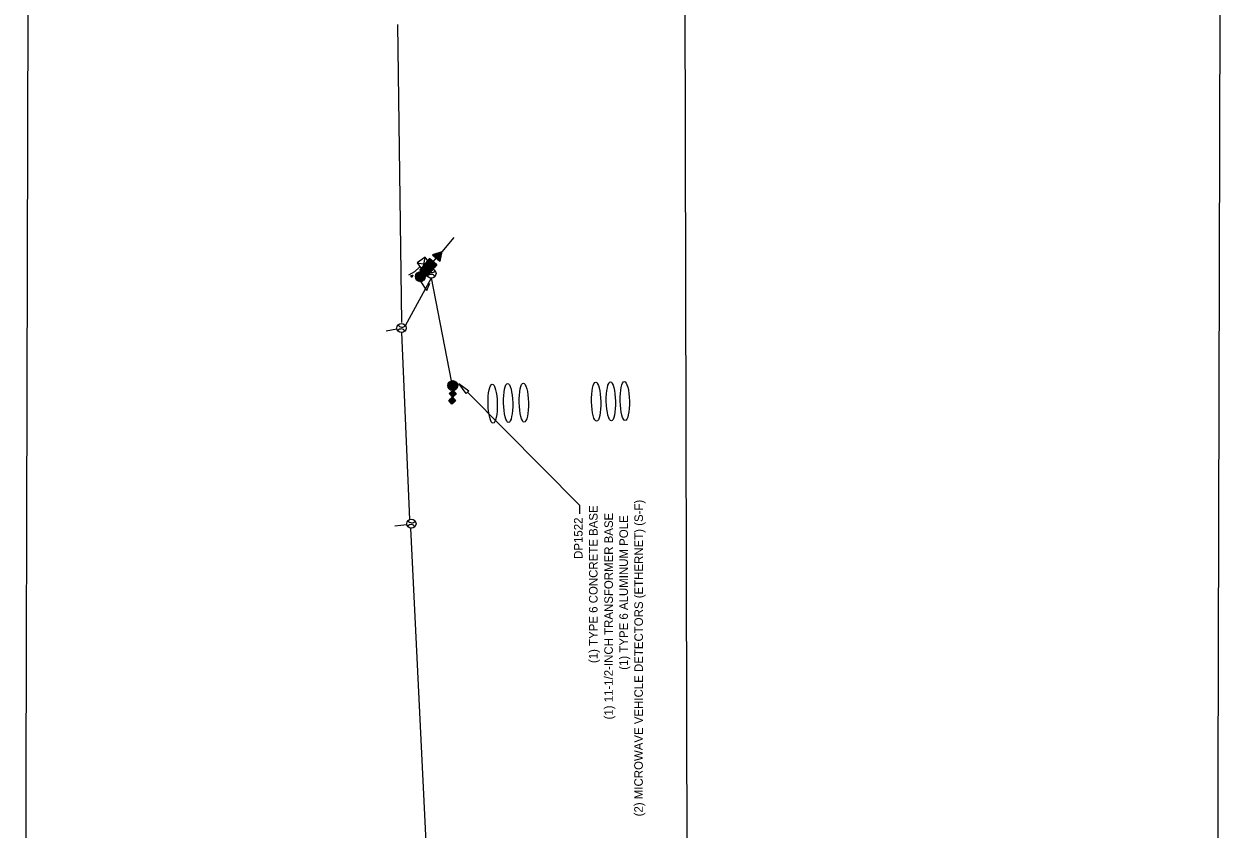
# Model space of a CAD drawing. Extents: x 601462 to 605493, y 331960 to 402715.
# Drawn here: x 602790 to 603769, y 376234 to 376893 of the extents above; entities that cross this region are included whole.
import ezdxf

# ---------------------------------------------------------------- set-up
doc = ezdxf.new("R2010")
doc.units = 0
for name, color, linetype in [('Default', 7, 'Continuous'), ('P_FTMS', 7, 'Continuous'), ('P_FTMSConduit', 7, 'Continuous'), ('P_MISC_TXT_1A (Construction)', 7, 'Continuous')]:
    doc.layers.add(name, color=color, linetype=linetype)

# ---------------------------------------------------------------- blocks, each defined once
blk = doc.blocks.new('FMB')
at = {"layer": 'P_FTMS'}
for p, q in [((24.4, -24.4), (-24.4, 24.4)), ((-24.4, -24.4), (24.4, 24.4))]:
    blk.add_line(p, q, dxfattribs=at)
blk.add_lwpolyline([(24.4, -24.4), (24.4, 24.4), (-24.4, 24.4), (-24.4, -24.4)], close=True, dxfattribs=at)
blk = doc.blocks.new('POINT_DISPLAY')
at = {"layer": 'Default'}
blk.add_line((0, 0), (0, 0), dxfattribs=at)
blk = doc.blocks.new('_U229')
at = {"layer": 'P_FTMS'}
for p, q in [((-4.5, 3.2), (1.5, -0.2)), ((-4.4, 2.8), (1.3, -0.4)), ((-4.3, 3.5), (1.8, 0)), ((-3.9, 3.4), (-4.3, 2.6)), ((-4.3, 2.4), (1, -0.6)), ((-3.5, 3.4), (-4.2, 2.2)), ((-4.2, 2), (0.7, -0.8)), ((-3.2, 3.3), (-4.1, 1.7)), ((-4.1, 1.6), (0.5, -1)), ((-2.9, 3.3), (-4, 1.3)), ((-4, 1.2), (0.2, -1.2)), ((-2.6, 3.2), (-3.9, 0.9)), ((-2.2, 3.2), (-3.8, 0.5)), ((-3.8, 0.7), (0, -1.4)), ((-1.9, 3.2), (-3.7, 0.1)), ((-3.7, 0.3), (-0.3, -1.6)), ((-3.5, 3.4), (2, 0.2)), ((-1.6, 3.1), (-3.5, -0.3)), ((-1.3, 3.1), (-3.4, -0.7)), ((-0.9, 3), (-3.3, -1.2)), ((-0.6, 3), (-3.2, -1.6)), ((-0.3, 2.9), (-3.1, -2)), ((0, 2.9), (-3, -2.4)), ((0.4, 2.8), (-2.9, -2.8)), ((-2.7, 3.3), (2.3, 0.4)), ((0.7, 2.8), (-2.7, -3.2)), ((1, 2.8), (-2.5, -3.4)), ((-1.9, 3.2), (2.5, 0.6)), ((1.3, 2.7), (-1.8, -2.9)), ((1.7, 2.7), (-1.2, -2.3)), ((-1.1, 3), (2.8, 0.8)), ((2, 2.6), (-0.5, -1.8)), ((-0.3, 2.9), (3.1, 1)), ((2.3, 2.6), (0.1, -1.3)), ((0.5, 2.8), (3.3, 1.2)), ((2.6, 2.5), (0.7, -0.8)), ((1.3, 2.7), (3.6, 1.4)), ((3, 2.5), (1.4, -0.3)), ((3.3, 2.4), (2, 0.2)), ((2.2, 2.6), (3.8, 1.6)), ((3.6, 2.4), (2.7, 0.7)), ((3, 2.5), (4.1, 1.8)), ((3.9, 2.3), (3.3, 1.2)), ((3.8, 2.4), (4.3, 2.1)), ((4.3, 2.3), (4, 1.7)), ((-3.6, -0.1), (-0.5, -1.8)), ((-3.5, -0.5), (-0.8, -2)), ((-3.4, -0.9), (-1.1, -2.2)), ((-3.3, -1.3), (-1.3, -2.4)), ((-3.2, -1.7), (-1.6, -2.7)), ((-3, -2.2), (-1.8, -2.9)), ((-2.9, -2.6), (-2.1, -3.1)), ((-2.8, -3), (-2.3, -3.3)), ((-2.7, -3.4), (-2.6, -3.5))]:
    blk.add_line(p, q, dxfattribs=at)
blk.add_lwpolyline([(-4.6, 3.5), (4.6, 2.3), (-2.7, -3.5)], close=True, dxfattribs=at)
blk.add_blockref('POINT_DISPLAY', (4.6, 2.3), dxfattribs=at)
blk = doc.blocks.new('_U231')
at = {"layer": 'P_FTMS'}
for p, q in [((12.1, 1.6), (-12.2, -0.1)), ((11.8, 3), (-12.1, 1.4)), ((11.9, 2.3), (-12.1, 0.6)), ((12.1, 0.8), (-12.1, -0.8)), ((12.1, 0.1), (-12.1, -1.6)), ((11.6, 3.7), (-12, 2.1)), ((-11.9, 2.5), (-11.4, -4.2)), ((11.3, 4.4), (-11.8, 2.9)), ((11, 5.2), (-11.6, 3.6)), ((10.6, 5.9), (-11.4, 4.4)), ((-11.3, 4.5), (-10.6, -6)), ((10.2, 6.6), (-11, 5.1)), ((9.8, 7.3), (-10.7, 5.9)), ((-10.7, 5.9), (-9.8, -7.2)), ((9.2, 8), (-10.2, 6.6)), ((-10, 6.9), (-9, -8.2)), ((8.6, 8.6), (-9.7, 7.4)), ((-9.3, 7.8), (-8.2, -9)), ((7.8, 9.3), (-9, 8.2)), ((-8.6, 8.5), (-7.4, -9.6)), ((6.9, 10), (-8.2, 9)), ((-8, 9.2), (-6.6, -10.2)), ((-7.3, 9.7), (-5.9, -10.6)), ((5.8, 10.7), (-7.2, 9.8)), ((-6.6, 10.3), (-5.1, -11)), ((4.5, 11.3), (-6, 10.6)), ((-5.9, 10.7), (-4.4, -11.4)), ((-5.1, 11), (-3.6, -11.6)), ((-4.4, 11.3), (-2.9, -11.8)), ((2.5, 11.9), (-4.1, 11.5)), ((-3.7, 11.6), (-2.1, -12)), ((-3, 11.8), (-1.4, -12.1)), ((-2.3, 12), (-0.6, -12.2)), ((-1.6, 12.1), (0.1, -12.2)), ((-0.8, 12.1), (0.8, -12.1)), ((-0.1, 12.2), (1.6, -12.1)), ((0.6, 12.1), (2.3, -11.9)), ((1.4, 12.1), (3, -11.8)), ((2.1, 12), (3.7, -11.6)), ((2.9, 11.8), (4.4, -11.3)), ((3.6, 11.6), (5.1, -11)), ((4.4, 11.3), (5.9, -10.7)), ((5.1, 11), (6.6, -10.2)), ((5.9, 10.6), (7.3, -9.8)), ((6.6, 10.2), (8, -9.2)), ((7.4, 9.7), (8.6, -8.6)), ((8.2, 9), (9.3, -7.8)), ((9, 8.2), (10, -6.9)), ((9.8, 7.2), (10.7, -5.8)), ((10.6, 5.9), (11.3, -4.5)), ((11.5, 4), (11.9, -2.5)), ((12.1, -0.6), (-12, -2.3)), ((12.1, -1.4), (-11.8, -3)), ((12, -2.1), (-11.6, -3.7)), ((11.8, -2.9), (-11.3, -4.4)), ((11.6, -3.6), (-11, -5.1)), ((11.3, -4.4), (-10.7, -5.9)), ((11.1, -5.1), (-10.2, -6.6)), ((10.6, -5.9), (-9.8, -7.3)), ((10.2, -6.6), (-9.2, -8)), ((9.6, -7.4), (-8.5, -8.6)), ((9, -8.2), (-7.8, -9.3)), ((8.2, -9), (-6.9, -10)), ((7.3, -9.8), (-5.8, -10.7)), ((6, -10.6), (-4.5, -11.3)), ((4.1, -11.5), (-2.6, -11.9))]:
    blk.add_line(p, q, dxfattribs=at)
blk.add_circle((0, 0), 12.2, dxfattribs=at)
blk = doc.blocks.new('FMD')
at = {"layer": 'P_FTMS'}
for p, q in [((16.9, 17.6), (-16.9, 17.6)), ((-16.1, 16.1), (-16.1, 18.4)), ((16.1, 16.1), (-16.1, 16.1)), ((15.5, 19), (-15.5, 19)), ((-14.6, 14.6), (-14.6, 19.9)), ((14.6, 14.6), (-14.6, 14.6)), ((14, 20.5), (-14, 20.5)), ((-13.2, 13.2), (-13.2, 21.3)), ((13.2, 13.2), (-13.2, 13.2)), ((12.5, 21.9), (-12.5, 21.9)), ((-11.7, 11.7), (-11.7, 22.8)), ((11.7, 11.7), (-11.7, 11.7)), ((11.1, 23.4), (-11.1, 23.4)), ((-10.2, 10.2), (-10.2, 24.2)), ((10.2, 10.2), (-10.2, 10.2)), ((9.6, 24.9), (-9.6, 24.9)), ((-8.8, 8.8), (-8.8, 25.7)), ((8.8, 8.8), (-8.8, 8.8)), ((8.2, 26.3), (-8.2, 26.3)), ((-7.3, 7.3), (-7.3, 27.2)), ((7.3, 7.3), (-7.3, 7.3)), ((6.7, 27.8), (-6.7, 27.8)), ((-5.9, 5.9), (-5.9, 28.6)), ((5.9, 5.9), (-5.9, 5.9)), ((5.2, 29.3), (-5.2, 29.3)), ((-4.4, 4.4), (-4.4, 30.1)), ((4.4, 4.4), (-4.4, 4.4)), ((3.8, 30.7), (-3.8, 30.7)), ((-2.9, 2.9), (-2.9, 31.6)), ((2.9, 2.9), (-2.9, 2.9)), ((2.3, 32.2), (-2.3, 32.2)), ((-1.5, 1.5), (-1.5, 33)), ((1.5, 1.5), (-1.5, 1.5)), ((0.8, 33.6), (-0.8, 33.6)), ((0, 0), (0, 34.5)), ((1.5, 1.5), (1.5, 33)), ((2.9, 2.9), (2.9, 31.6)), ((4.4, 4.4), (4.4, 30.1)), ((5.9, 5.9), (5.9, 28.6)), ((7.3, 7.3), (7.3, 27.2)), ((8.8, 8.8), (8.8, 25.7)), ((10.2, 10.2), (10.2, 24.2)), ((11.7, 11.7), (11.7, 22.8)), ((13.2, 13.2), (13.2, 21.3)), ((14.6, 14.6), (14.6, 19.9)), ((16.1, 16.1), (16.1, 18.4))]:
    blk.add_line(p, q, dxfattribs=at)
blk.add_lwpolyline([(-17.2, 17.2), (0, 34.5), (17.2, 17.2), (0, 0)], close=True, dxfattribs=at)

msp = doc.modelspace()

# ---------------------------------------------------------------- linework, layer by layer
at = {"layer": 'P_FTMS'}
for p, q in [((603141.66, 376718.23), (603131.72, 376706.73)), ((603119.37, 376698.52), (603124.15, 376698.87)), ((603119.59, 376698.78), (603123.9, 376699.09)), ((603119.59, 376698.78), (603120.41, 376687.5)), ((603119.81, 376699.04), (603123.64, 376699.32)), ((603119.81, 376699.04), (603120.63, 376687.75)), ((603120.03, 376699.29), (603123.38, 376699.54)), ((603120.03, 376699.29), (603120.85, 376688.01)), ((603120.25, 376699.55), (603123.13, 376699.76)), ((603120.25, 376699.55), (603121.08, 376688.27)), ((603120.48, 376699.81), (603122.87, 376699.98)), ((603120.48, 376699.81), (603121.3, 376688.52)), ((603120.7, 376700.06), (603122.61, 376700.2)), ((603120.7, 376700.06), (603121.52, 376688.78)), ((603120.92, 376700.32), (603122.36, 376700.43)), ((603120.92, 376700.32), (603121.74, 376689.04)), ((603121.14, 376700.58), (603122.1, 376700.65)), ((603121.14, 376700.58), (603121.96, 376689.29)), ((603121.36, 376700.83), (603121.84, 376700.87)), ((603121.36, 376700.83), (603122.19, 376689.55)), ((603121.58, 376701.09), (603122.41, 376689.81)), ((603121.84, 376700.87), (603122.63, 376690.06)), ((603122.1, 376700.65), (603122.85, 376690.32)), ((603122.36, 376700.43), (603123.07, 376690.58)), ((603122.61, 376700.2), (603123.3, 376690.83)), ((603122.87, 376699.98), (603123.52, 376691.09)), ((603123.13, 376699.76), (603123.74, 376691.35)), ((603123.38, 376699.54), (603123.96, 376691.6)), ((603123.64, 376699.32), (603124.18, 376691.86)), ((603123.9, 376699.09), (603124.41, 376692.12)), ((603124.15, 376698.87), (603124.63, 376692.38)), ((603124.21, 376704.12), (603124.21, 376704.11)), ((603124.31, 376704.02), (603131.3, 376704.53)), ((603124.44, 376704.2), (603124.47, 376703.89)), ((603124.57, 376703.8), (603131.25, 376704.29)), ((603124.61, 376698.48), (603127.23, 376701.5)), ((603124.68, 376704.28), (603124.72, 376703.66)), ((603124.7, 376704.29), (603131.35, 376704.78)), ((603124.82, 376703.58), (603131.21, 376704.05)), ((603124.91, 376704.36), (603124.98, 376703.44)), ((603125.08, 376703.36), (603131.16, 376703.8)), ((603125.15, 376704.45), (603125.24, 376703.22)), ((603125.34, 376703.14), (603131.11, 376703.56)), ((603125.38, 376704.53), (603125.49, 376703)), ((603125.58, 376704.6), (603131.39, 376705.02)), ((603125.59, 376702.91), (603131.07, 376703.31)), ((603125.62, 376704.61), (603125.75, 376702.78)), ((603125.85, 376704.69), (603126.01, 376702.55)), ((603125.85, 376702.69), (603131.02, 376703.07)), ((603126.09, 376704.77), (603126.26, 376702.33)), ((603126.11, 376702.47), (603130.97, 376702.82)), ((603126.32, 376704.85), (603126.52, 376702.11)), ((603126.36, 376702.25), (603130.93, 376702.58)), ((603126.46, 376704.9), (603131.44, 376705.27)), ((603126.56, 376704.94), (603126.78, 376701.89)), ((603126.62, 376702.03), (603130.88, 376702.34)), ((603126.79, 376705.02), (603127.04, 376701.67)), ((603126.88, 376701.8), (603130.83, 376702.09)), ((603127.03, 376705.1), (603127.29, 376701.45)), ((603127.13, 376701.58), (603130.79, 376701.85)), ((603127.26, 376705.18), (603127.55, 376701.22)), ((603127.34, 376705.21), (603131.49, 376705.51)), ((603127.39, 376701.36), (603130.74, 376701.6)), ((603127.49, 376705.26), (603127.81, 376701)), ((603127.65, 376701.14), (603130.69, 376701.36)), ((603127.73, 376705.34), (603128.06, 376700.78)), ((603127.9, 376700.92), (603130.65, 376701.12)), ((603127.96, 376705.43), (603128.32, 376700.56)), ((603128.16, 376700.69), (603130.6, 376700.87)), ((603128.2, 376705.51), (603128.58, 376700.34)), ((603128.21, 376705.51), (603131.53, 376705.75)), ((603128.42, 376700.47), (603130.55, 376700.63)), ((603128.43, 376705.59), (603128.83, 376700.11)), ((603128.67, 376705.67), (603129.09, 376699.89)), ((603128.67, 376700.25), (603130.51, 376700.38)), ((603128.9, 376705.75), (603129.35, 376699.67)), ((603128.93, 376700.03), (603130.46, 376700.14)), ((603129.09, 376705.82), (603131.58, 376706)), ((603129.14, 376705.83), (603129.6, 376699.45)), ((603129.19, 376699.81), (603130.41, 376699.9)), ((603129.37, 376705.91), (603129.86, 376699.23)), ((603129.44, 376699.59), (603130.37, 376699.65)), ((603129.61, 376706), (603130.12, 376699)), ((603129.7, 376699.36), (603130.32, 376699.41)), ((603129.84, 376706.08), (603130.33, 376699.44)), ((603129.96, 376699.14), (603130.27, 376699.16)), ((603129.97, 376706.12), (603131.63, 376706.24)), ((603130.08, 376706.16), (603130.5, 376700.35)), ((603130.22, 376698.92), (603130.23, 376698.92)), ((603130.31, 376706.24), (603130.67, 376701.26)), ((603130.55, 376706.32), (603130.85, 376702.17)), ((603130.78, 376706.4), (603131.02, 376703.09)), ((603130.84, 376706.43), (603131.67, 376706.49)), ((603131.01, 376706.48), (603131.2, 376704)), ((603131.25, 376706.57), (603131.37, 376704.91)), ((603131.48, 376706.65), (603131.54, 376705.82)), ((603131.72, 376706.73), (603131.72, 376706.73)), ((603110.8, 376688.53), (603117.15, 376688.99)), ((603110.97, 376688.78), (603116.95, 376689.22)), ((603111.08, 376688.91), (603111.48, 376683.41)), ((603111.19, 376689.04), (603116.69, 376689.44)), ((603111.3, 376689.16), (603111.74, 376683.19)), ((603111.44, 376689.3), (603116.41, 376689.66)), ((603111.52, 376689.37), (603111.99, 376683.02)), ((603111.75, 376689.56), (603112.24, 376682.85)), ((603111.76, 376689.56), (603116.04, 376689.88)), ((603111.98, 376689.72), (603112.49, 376682.74)), ((603112.18, 376689.83), (603115.6, 376690.08)), ((603112.21, 376689.85), (603112.74, 376682.63)), ((603112.44, 376689.98), (603112.99, 376682.55)), ((603112.68, 376690.07), (603113.23, 376682.49)), ((603112.81, 376690.12), (603114.95, 376690.28)), ((603112.91, 376690.16), (603113.48, 376682.43)), ((603113.15, 376690.24), (603113.72, 376682.4)), ((603113.38, 376690.28), (603113.96, 376682.39)), ((603113.62, 376690.32), (603114.2, 376682.37)), ((603113.82, 376692.1), (603125.1, 376692.92)), ((603113.82, 376692.1), (603113.83, 376691.93)), ((603113.86, 376690.35), (603114.44, 376682.39)), ((603113.9, 376691.87), (603124.88, 376692.67)), ((603114.04, 376692.36), (603125.32, 376693.18)), ((603114.04, 376692.36), (603114.09, 376691.71)), ((603114.1, 376690.35), (603114.68, 376682.41)), ((603114.16, 376691.65), (603124.66, 376692.41)), ((603114.26, 376692.62), (603125.55, 376693.44)), ((603114.26, 376692.62), (603114.34, 376691.49)), ((603114.34, 376690.36), (603114.92, 376682.45)), ((603114.42, 376691.42), (603124.44, 376692.15)), ((603114.48, 376692.87), (603125.77, 376693.7)), ((603114.48, 376692.87), (603114.6, 376691.26)), ((603114.58, 376690.34), (603115.15, 376682.51)), ((603114.67, 376691.2), (603124.21, 376691.9)), ((603114.71, 376693.13), (603125.99, 376693.95)), ((603114.71, 376693.13), (603114.86, 376691.04)), ((603114.83, 376690.3), (603115.39, 376682.57)), ((603114.93, 376693.39), (603126.21, 376694.21)), ((603114.93, 376693.39), (603115.12, 376690.82)), ((603114.93, 376690.98), (603123.99, 376691.64)), ((603115.07, 376690.26), (603115.62, 376682.66)), ((603115.15, 376693.64), (603126.43, 376694.47)), ((603115.15, 376693.64), (603115.37, 376690.6)), ((603115.19, 376690.76), (603123.77, 376691.38)), ((603115.32, 376690.18), (603115.86, 376682.77)), ((603115.37, 376693.9), (603126.66, 376694.72)), ((603115.37, 376693.9), (603115.63, 376690.38)), ((603115.45, 376690.54), (603123.55, 376691.13)), ((603115.56, 376690.1), (603116.09, 376682.87)), ((603115.59, 376694.16), (603126.88, 376694.98)), ((603115.59, 376694.16), (603115.89, 376690.16)), ((603115.7, 376690.31), (603123.33, 376690.87)), ((603115.81, 376690), (603116.32, 376683.02)), ((603115.82, 376694.41), (603127.1, 376695.24)), ((603115.82, 376694.41), (603116.14, 376689.93)), ((603115.96, 376690.09), (603123.11, 376690.61)), ((603116.04, 376694.67), (603127.32, 376695.49)), ((603116.04, 376694.67), (603116.4, 376689.71)), ((603116.06, 376689.87), (603116.55, 376683.18)), ((603116.22, 376689.87), (603122.88, 376690.36)), ((603116.26, 376694.93), (603127.54, 376695.75)), ((603116.26, 376694.93), (603116.66, 376689.49)), ((603116.31, 376689.73), (603116.78, 376683.36)), ((603116.47, 376689.65), (603122.66, 376690.1)), ((603116.48, 376695.18), (603127.49, 376695.99)), ((603116.48, 376695.18), (603116.91, 376689.27)), ((603116.57, 376689.54), (603117, 376683.58)), ((603116.7, 376695.44), (603127.24, 376696.21)), ((603116.7, 376695.44), (603117.17, 376689.05)), ((603116.73, 376689.43), (603122.44, 376689.84)), ((603116.82, 376689.34), (603117.22, 376683.82)), ((603116.93, 376695.7), (603126.98, 376696.43)), ((603116.93, 376695.7), (603117.43, 376688.82)), ((603116.99, 376689.2), (603122.22, 376689.59)), ((603117.08, 376689.07), (603117.44, 376684.12)), ((603117.15, 376695.95), (603126.72, 376696.65)), ((603117.15, 376695.95), (603117.68, 376688.6)), ((603117.24, 376688.98), (603122, 376689.33)), ((603117.37, 376696.21), (603126.46, 376696.87)), ((603117.37, 376696.21), (603117.94, 376688.38)), ((603117.5, 376688.76), (603121.77, 376689.07)), ((603117.59, 376696.47), (603126.21, 376697.1)), ((603117.59, 376696.47), (603118.2, 376688.16)), ((603117.81, 376696.72), (603125.95, 376697.32)), ((603117.81, 376696.72), (603118.45, 376687.94)), ((603118.03, 376696.98), (603125.69, 376697.54)), ((603118.03, 376696.98), (603118.71, 376687.71)), ((603118.26, 376697.24), (603125.44, 376697.76)), ((603118.26, 376697.24), (603118.97, 376687.49)), ((603118.48, 376697.49), (603125.18, 376697.98)), ((603118.48, 376697.49), (603119.22, 376687.27)), ((603118.7, 376697.75), (603124.92, 376698.21)), ((603118.7, 376697.75), (603119.48, 376687.05)), ((603118.92, 376698.01), (603124.67, 376698.43)), ((603118.92, 376698.01), (603119.74, 376686.83)), ((603119.14, 376698.27), (603124.41, 376698.65)), ((603119.14, 376698.27), (603119.97, 376686.98)), ((603119.37, 376698.52), (603120.19, 376687.24)), ((603119.89, 376693.01), (603119.72, 376692.81)), ((603119.89, 376693.01), (603119.89, 376693.01)), ((603124.41, 376698.65), (603124.85, 376692.63)), ((603124.67, 376698.43), (603125.07, 376692.89)), ((603124.92, 376698.21), (603125.29, 376693.15)), ((603125.18, 376697.98), (603125.51, 376693.4)), ((603125.44, 376697.76), (603125.74, 376693.66)), ((603125.69, 376697.54), (603125.96, 376693.92)), ((603125.95, 376697.32), (603126.18, 376694.17)), ((603126.21, 376697.1), (603126.4, 376694.43)), ((603126.46, 376696.87), (603126.62, 376694.69)), ((603126.72, 376696.65), (603126.85, 376694.94)), ((603126.98, 376696.43), (603127.07, 376695.2)), ((603127.24, 376696.21), (603127.29, 376695.46)), ((603127.49, 376695.99), (603127.51, 376695.71)), ((603110.16, 376686.32), (603118.11, 376686.9)), ((603110.17, 376686.56), (603118.06, 376687.13)), ((603110.17, 376686.08), (603118.13, 376686.66)), ((603110.18, 376686.8), (603118.01, 376687.37)), ((603110.2, 376685.84), (603118.14, 376686.42)), ((603110.22, 376687.04), (603117.95, 376687.61)), ((603110.23, 376685.6), (603118.14, 376686.18)), ((603110.24, 376687.15), (603110.4, 376685.01)), ((603110.27, 376687.29), (603117.85, 376687.84)), ((603110.29, 376685.36), (603118.11, 376685.94)), ((603110.33, 376687.53), (603117.76, 376688.07)), ((603110.36, 376685.13), (603118.08, 376685.69)), ((603110.42, 376687.78), (603117.64, 376688.31)), ((603110.44, 376687.81), (603110.69, 376684.39)), ((603110.44, 376684.89), (603118.03, 376685.45)), ((603110.52, 376688.03), (603117.49, 376688.54)), ((603110.55, 376684.66), (603117.96, 376685.2)), ((603110.64, 376688.27), (603110.96, 376683.99)), ((603110.65, 376688.28), (603117.35, 376688.77)), ((603110.67, 376684.43), (603117.89, 376684.96)), ((603110.8, 376684.2), (603117.78, 376684.71)), ((603110.86, 376688.62), (603111.22, 376683.65)), ((603110.97, 376683.97), (603117.65, 376684.46)), ((603111.14, 376683.74), (603117.51, 376684.21)), ((603111.36, 376683.52), (603117.32, 376683.95)), ((603111.6, 376683.29), (603117.12, 376683.7)), ((603111.9, 376683.08), (603116.85, 376683.44)), ((603112.23, 376682.86), (603116.54, 376683.17)), ((603112.7, 376682.65), (603116.15, 376682.9)), ((603113.35, 376682.46), (603115.54, 376682.62)), ((603117.34, 376688.78), (603117.66, 376684.47)), ((603117.62, 376688.34), (603117.87, 376684.89)), ((603117.76, 376688.54), (603121.55, 376688.82)), ((603117.9, 376687.73), (603118.06, 376685.54)), ((603118.01, 376688.32), (603121.33, 376688.56)), ((603118.27, 376688.09), (603121.11, 376688.3)), ((603118.53, 376687.87), (603120.89, 376688.05)), ((603118.78, 376687.65), (603120.66, 376687.79)), ((603119.04, 376687.43), (603120.44, 376687.53)), ((603119.3, 376687.21), (603120.22, 376687.27)), ((603119.55, 376686.99), (603120, 376687.02))]:
    msp.add_line(p, q, dxfattribs=at)
for points in [[(603119.79, 376686.78), (603127.64, 376695.86), (603121.58, 376701.09), (603113.74, 376692.01)], [(603124.2, 376704.12), (603130.22, 376698.91), (603131.72, 376706.73)]]:
    msp.add_lwpolyline(points, close=True, dxfattribs=at)
for centre, radius in [((603114.15, 376686.37), 4), ((603123.25, 376688.92), 3.75), ((603098.8, 376644.25), 3.75), ((603106.89, 376484.2), 3.75)]:
    msp.add_circle(centre, radius, dxfattribs=at)
for centre, start, end in [((603123.58, 376693.41), 212.62987, 318.88552), ((603122.92, 376684.44), 32.62987, 138.88552), ((603098.46, 376639.76), 32.62987, 138.88552), ((603099.13, 376648.74), 212.62987, 318.88552), ((603106.55, 376479.71), 32.62987, 138.88552), ((603107.22, 376488.69), 212.62987, 318.88552)]:
    msp.add_arc(centre, 3.75, start, end, dxfattribs=at)
for centre in [(603173.35, 376582.43), (603185.95, 376583.02), (603198.78, 376583.31), (603257.98, 376583.97), (603270.02, 376584.24), (603281.37, 376584.49)]:
    msp.add_ellipse(centre, major_axis=(-0.36, 15.98), ratio=0.23471, dxfattribs=at)
at = {"layer": 'P_FTMSConduit'}
for p, q in [((603329.33, 377421.42), (603332.94, 375897.8)), ((603099.13, 376648.74), (603095.84, 376892.65)), ((603109.34, 376690.35), (603104.4, 376687.41)), ((603113.79, 376694.41), (603109.34, 376690.35)), ((603101.95, 376646.28), (603123.35, 376685.44)), ((603119.61, 376674.85), (603114.98, 376682.12)), ((603119.32, 376688.67), (603117.64, 376688.1)), ((603119.61, 376674.85), (603121.81, 376680.93)), ((603139.55, 376601.08), (603123.35, 376685.44)), ((603086.13, 376641.94), (603095.08, 376643.73)), ((603105.53, 376487.7), (603099, 376640.5)), ((603093.24, 376482.52), (603103.17, 376483.68)), ((603120.69, 376189.1), (603106.3, 376480.49))]:
    msp.add_line(p, q, dxfattribs=at)
msp.add_lwpolyline([(603151.55, 376590.62), (603145.71, 376598.9), (603153.92, 376592.97)], close=True, dxfattribs=at)
for points in [[(603152.74, 376591.8), (603244.22, 376499.35)], [(603244.22, 376499.35), (603244.21, 376492.35)]]:
    msp.add_lwpolyline(points, dxfattribs=at)
at = {"layer": 'P_MISC_TXT_1A (Construction)'}
msp.add_lwpolyline([(603764.98, 375644.6), (603769.03, 377219.59), (602794.03, 377222.1), (602789.98, 375647.11)], close=True, dxfattribs=at)
msp.add_lwpolyline([(603764.98, 375644.6), (603769.03, 377219.59), (602794.03, 377222.1), (602789.98, 375647.11)], close=True, dxfattribs=at)

# ---------------------------------------------------------------- block references
at = {"layer": 'P_FTMS'}
for name, p, xscale, yscale, rotation in [('FMB', (603117.06, 376696.72), 0.1640416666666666, 0.1640416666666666, -54.79289734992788), ('_U229', (603107.43, 376686.75), 0.19684999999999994, 0.19684999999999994, 20.861391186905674), ('_U231', (603140.7, 376597.25), 0.3280833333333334, 0.32808333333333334, 179.05577776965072), ('FMD', (603143.48, 376590.19), 0.16404166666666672, 0.16404166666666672, 84.94864200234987), ('FMD', (603143, 376584.59), 0.16404166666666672, 0.16404166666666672, 84.94864200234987)]:
    msp.add_blockref(name, p, dxfattribs=dict(at, xscale=xscale, yscale=yscale, rotation=rotation))

# ---------------------------------------------------------------- texts
at = {"layer": 'P_FTMSConduit'}
for s, p in [('(2) MICROWAVE VEHICLE DETECTORS (ETHERNET) (S-F)', (603296.09, 376244.82)), ('(1) TYPE 6 CONCRETE BASE', (603259.06, 376370.21)), ('DP1522', (603246.83, 376455.41)), ('(1) 11-1/2-INCH TRANSFORMER BASE', (603271.56, 376324.08)), ('(1) TYPE 6 ALUMINUM POLE', (603283.88, 376364.68))]:
    msp.add_text(s, height=7, rotation=89.96038, dxfattribs=at).set_placement(p)

doc.saveas('drawing.dxf')
